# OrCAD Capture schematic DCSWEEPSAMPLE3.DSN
size A
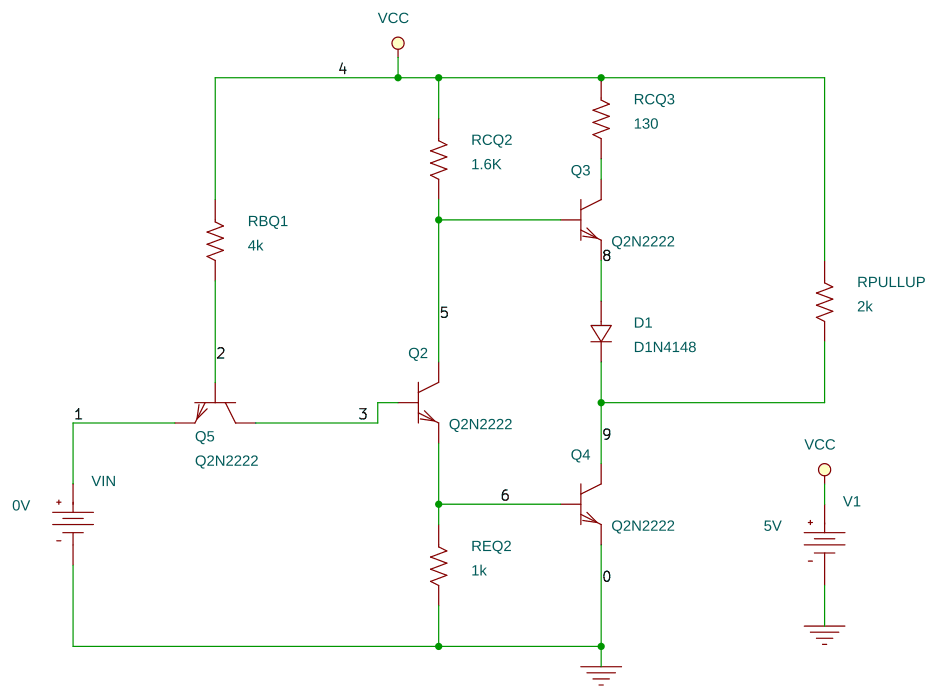
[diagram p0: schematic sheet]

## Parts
D1  D1N4148  [DO-35]
Q2  Q2N2222  [TO18]
Q3  Q2N2222  [TO18]
Q4  Q2N2222  [TO18]
Q5  Q2N2222  [TO18]
RBQ1  4k  [AX/RC05]
RCQ2  1.6K  [AX/RC05]
RCQ3  130  [AX/RC05]
REQ2  1k  [AX/RC05]
RPULLUP  2k  [AX/RC05]
V1  VDC
VIN  VDC

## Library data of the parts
D1 = D1N4148
Q2-Q5 = Q2N2222
RBQ1 RCQ2 RCQ3 REQ2 RPULLUP = R
V1 = VDC: DC: 5V
VIN = VDC: DC: 0V

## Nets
VCC: RBQ1.1 RCQ2.1 RCQ3.1 RPULLUP.1 V1.0(+)
0: Q4.1(e) REQ2.2 V1.1(-) VIN.1(-)
1: Q5.1(e) VIN.0(+)
2: Q5.2(b) RBQ1.2
3: Q2.2(b) Q5.3(c)
5: Q2.3(c) Q3.2(b) RCQ2.2
6: Q2.1(e) Q4.2(b) REQ2.1
8: D1.1 Q3.1(e)
9: D1.2 Q4.3(c) RPULLUP.2
N03234: Q3.3(c) RCQ3.2
